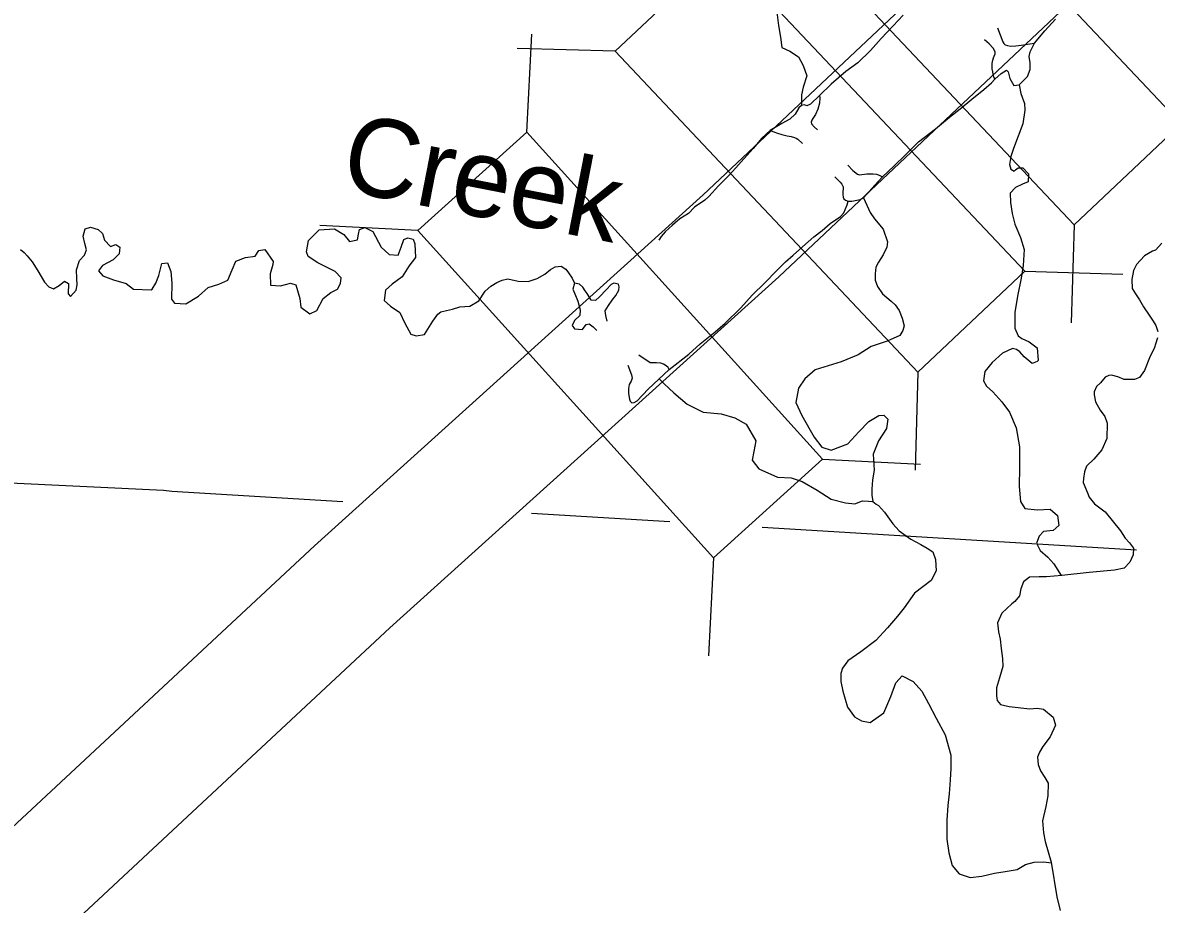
# Model space of a CAD drawing. Extents: x -492261 to -432772, y 1441225 to 1452922.
# Drawn here: x -459293.9 to -459217.6, y 1452255.8 to 1452315.2 of the extents above; entities that cross this region are included whole.
import ezdxf

# ---------------------------------------------------------------- set-up
doc = ezdxf.new("R2010")
doc.units = 0
doc.layers.add('Default', color=7, linetype='Continuous')

msp = doc.modelspace()

# ---------------------------------------------------------------- linework, layer by layer
at = {"layer": 'Default'}
for p, q in [((-459259.942, 1452307.832), (-459259.608, 1452314.423)), ((-459253.993, 1452313.271), (-459260.59, 1452313.464)), ((-459267.287, 1452301.194), (-459273.879, 1452301.528)), ((-459223.1, 1452301.582), (-459223.293, 1452294.985)), ((-459226.413, 1452298.458), (-459219.815, 1452298.265)), ((-459233.615, 1452291.665), (-459233.807, 1452285.068)), ((-459240.031, 1452285.795), (-459233.439, 1452285.461)), ((-459247.376, 1452279.158), (-459247.71, 1452272.566))]:
    msp.add_line(p, q, dxfattribs=at)
for points in [[(-459243.478, 1452323.188), (-459223.1, 1452301.582), (-459215.898, 1452308.375), (-459236.276, 1452329.981)], [(-459226.413, 1452298.458), (-459246.791, 1452320.063), (-459253.993, 1452313.271), (-459233.615, 1452291.665)], [(-459267.287, 1452301.194), (-459247.376, 1452279.158), (-459240.031, 1452285.795), (-459259.942, 1452307.832)]]:
    msp.add_lwpolyline(points, close=True, dxfattribs=at)
for points in [[(-459226.852, 1452323.611), (-459248.072, 1452303.597), (-459274.233, 1452279.959), (-459300.843, 1452255.178), (-459324.123, 1452234.249), (-459334.966, 1452224.74), (-459339.178, 1452220.722), (-459342.089, 1452218.162), (-459344.419, 1452216.641), (-459347.562, 1452215.217), (-459351.068, 1452213.62), (-459355.03, 1452212.272), (-459362.034, 1452210.587), (-459385.935, 1452204.007), (-459423.021, 1452192.768)], [(-459221.706, 1452318.155), (-459242.984, 1452298.086), (-459269.163, 1452274.432), (-459295.78, 1452249.645), (-459319.143, 1452228.64), (-459329.903, 1452219.205), (-459334.111, 1452215.19), (-459337.54, 1452212.176), (-459340.801, 1452210.046), (-459344.461, 1452208.389), (-459348.299, 1452206.64), (-459352.94, 1452205.061), (-459360.161, 1452203.323), (-459383.851, 1452196.802), (-459420.846, 1452185.59)], [(-459249.502, 1452318.521), (-459248.411, 1452317.678), (-459247.93, 1452317.066), (-459247.335, 1452316.421), (-459246.434, 1452316.774), (-459245.69, 1452317.787), (-459244.752, 1452318.154), (-459243.708, 1452317.936), (-459243.173, 1452317.213), (-459243.126, 1452316.087), (-459243.005, 1452315.001), (-459242.868, 1452314.216), (-459242.784, 1452313.53), (-459242.239, 1452313.271), (-459241.652, 1452312.901), (-459241.347, 1452312.321), (-459241.088, 1452311.628), (-459241.339, 1452310.856), (-459241.448, 1452310.339), (-459241.449, 1452309.615)], [(-459234.615, 1452315.702), (-459235.281, 1452314.993), (-459236.079, 1452314.141), (-459236.816, 1452313.317), (-459237.652, 1452312.489), (-459238.471, 1452311.9), (-459239.457, 1452311.055), (-459240.246, 1452310.304), (-459240.84, 1452309.709), (-459241.099, 1452309.588), (-459241.251, 1452309.671), (-459241.449, 1452309.615), (-459241.632, 1452309.459), (-459241.881, 1452309.038), (-459242.233, 1452308.701), (-459242.786, 1452308.409), (-459243.571, 1452307.933), (-459244.118, 1452307.428), (-459244.696, 1452306.733), (-459245.324, 1452306.025), (-459245.881, 1452305.431), (-459246.376, 1452304.89), (-459247.042, 1452304.205), (-459247.682, 1452303.484), (-459247.962, 1452303.237), (-459248.66, 1452302.777), (-459249.071, 1452302.338), (-459249.635, 1452301.983)], [(-459249.037, 1452292.874), (-459248.284, 1452293.573), (-459247.271, 1452294.369), (-459246.602, 1452294.966), (-459245.534, 1452295.989), (-459244.774, 1452296.852), (-459243.924, 1452297.667), (-459243.125, 1452298.494), (-459242.532, 1452299.088), (-459242.021, 1452299.543), (-459241.388, 1452300.101), (-459240.622, 1452300.764), (-459240.06, 1452301.194), (-459239.512, 1452301.662), (-459238.823, 1452302.134), (-459238.597, 1452302.38), (-459238.374, 1452302.924), (-459238.322, 1452303.169), (-459238.065, 1452303.182), (-459237.731, 1452303.233), (-459237.506, 1452303.297), (-459237.28, 1452303.41), (-459236.519, 1452304.261), (-459236.011, 1452304.79), (-459235.222, 1452305.566), (-459234.482, 1452306.278), (-459233.573, 1452307.171), (-459232.425, 1452308.046), (-459231.5, 1452308.838), (-459230.768, 1452309.4), (-459229.988, 1452310.038), (-459229.183, 1452310.689), (-459228.66, 1452311.144), (-459228.43, 1452311.389), (-459228.005, 1452311.766), (-459227.65, 1452312.002), (-459227.546, 1452311.892), (-459227.432, 1452311.445), (-459227.167, 1452310.965), (-459226.794, 1452311.001), (-459226.237, 1452311.57), (-459226.064, 1452312.039), (-459226.053, 1452312.49), (-459226.129, 1452312.926), (-459226.063, 1452313.229), (-459225.757, 1452313.827), (-459225.07, 1452314.638), (-459224.345, 1452315.437)], [(-459228.26, 1452314.857), (-459227.908, 1452313.898), (-459227.841, 1452313.794), (-459227.752, 1452313.703), (-459227.595, 1452313.655), (-459227.388, 1452313.626), (-459227.014, 1452313.642), (-459226.66, 1452313.68), (-459226.363, 1452313.718), (-459226.079, 1452313.762), (-459225.757, 1452313.827)], [(-459228.43, 1452311.389), (-459228.46, 1452311.449), (-459228.498, 1452311.543), (-459228.549, 1452311.733), (-459228.58, 1452311.897), (-459228.606, 1452312.087), (-459228.612, 1452312.454), (-459228.581, 1452312.674), (-459228.53, 1452312.833), (-459228.478, 1452312.953), (-459228.407, 1452313.093), (-459228.41, 1452313.205), (-459228.452, 1452313.329), (-459228.557, 1452313.489), (-459228.812, 1452313.766), (-459229.126, 1452314.049)], [(-459226.794, 1452311.001), (-459226.687, 1452310.418), (-459226.441, 1452309.762), (-459226.427, 1452309.311), (-459226.548, 1452308.38), (-459227.184, 1452306.72), (-459227.355, 1452306.188), (-459227.451, 1452305.646), (-459227.366, 1452305.336), (-459227.125, 1452305.205), (-459227.052, 1452305.283), (-459226.856, 1452305.414), (-459226.544, 1452305.424), (-459226.169, 1452305.009), (-459226.202, 1452304.47), (-459226.572, 1452304.32), (-459227.053, 1452304.093), (-459227.403, 1452303.718), (-459227.384, 1452303.08), (-459227.261, 1452302.357)], [(-459240.246, 1452310.304), (-459240.22, 1452310.128), (-459240.238, 1452309.785), (-459240.347, 1452309.378), (-459240.5, 1452309.017), (-459240.7, 1452308.74), (-459240.767, 1452308.639), (-459240.812, 1452308.504), (-459240.771, 1452308.379), (-459240.599, 1452308.189), (-459240.366, 1452307.989)], [(-459243.571, 1452307.933), (-459243.065, 1452307.748), (-459242.774, 1452307.656), (-459242.422, 1452307.573), (-459242.156, 1452307.526), (-459241.926, 1452307.47), (-459241.813, 1452307.421), (-459241.7, 1452307.345), (-459241.38, 1452307.058)], [(-459238.336, 1452305.61), (-459238.002, 1452305.253), (-459237.677, 1452304.988), (-459237.553, 1452304.961), (-459237.047, 1452305.021), (-459236.637, 1452305.021), (-459236.396, 1452304.985), (-459236.219, 1452304.933), (-459236.053, 1452304.845), (-459236.011, 1452304.79)], [(-459239.204, 1452304.813), (-459238.857, 1452304.454), (-459238.74, 1452304.313), (-459238.655, 1452304.147), (-459238.643, 1452304.004), (-459238.669, 1452303.796), (-459238.669, 1452303.625), (-459238.637, 1452303.452), (-459238.598, 1452303.342), (-459238.496, 1452303.252), (-459238.322, 1452303.169)], [(-459237.28, 1452303.41), (-459236.841, 1452302.419), (-459236.54, 1452301.99), (-459235.944, 1452301.294), (-459235.655, 1452300.439), (-459235.706, 1452300.078), (-459235.952, 1452299.553), (-459236.265, 1452299.075), (-459236.451, 1452298.735), (-459236.499, 1452298.277), (-459236.487, 1452297.857), (-459236.333, 1452297.431), (-459236.009, 1452296.945)], [(-459227.261, 1452302.357), (-459227.098, 1452301.634), (-459226.714, 1452300.721), (-459226.464, 1452299.927), (-459226.53, 1452298.848), (-459226.654, 1452297.992), (-459226.903, 1452296.769), (-459227.095, 1452295.686), (-459227.087, 1452294.634), (-459226.87, 1452294.102), (-459226.628, 1452293.934), (-459226.134, 1452293.711), (-459225.583, 1452293.289), (-459225.519, 1452292.439), (-459225.58, 1452292.375), (-459225.926, 1452292.252), (-459226.464, 1452292.698), (-459226.763, 1452293.04), (-459226.98, 1452293.196), (-459227.256, 1452293.25), (-459227.922, 1452292.941), (-459228.627, 1452292.318), (-459229.121, 1452291.714), (-459229.201, 1452291.073), (-459228.99, 1452290.716), (-459228.565, 1452290.328), (-459227.958, 1452289.67), (-459227.461, 1452288.959), (-459226.991, 1452287.921), (-459226.776, 1452286.638), (-459226.783, 1452285.259), (-459226.805, 1452283.956), (-459226.712, 1452282.944), (-459226.422, 1452282.477), (-459225.595, 1452282.389), (-459224.722, 1452282.442), (-459224.221, 1452282.018), (-459224.137, 1452281.332), (-459224.502, 1452281.008), (-459225.162, 1452280.937), (-459225.452, 1452280.615), (-459225.637, 1452280.146), (-459225.385, 1452279.652), (-459224.871, 1452279.205), (-459224.47, 1452278.753), (-459223.971, 1452277.959)], [(-459289.721, 1452299.549), (-459289.581, 1452299.892), (-459289.695, 1452300.327), (-459289.81, 1452300.812), (-459289.675, 1452301.304), (-459289.316, 1452301.416), (-459288.799, 1452301.269), (-459288.503, 1452300.99), (-459288.365, 1452300.556), (-459287.964, 1452300.117), (-459287.618, 1452300.253), (-459287.35, 1452300.073), (-459287.399, 1452299.621), (-459287.799, 1452299.233), (-459288.512, 1452298.847), (-459288.775, 1452298.488), (-459288.477, 1452298.147), (-459287.769, 1452297.868), (-459286.924, 1452297.631), (-459286.413, 1452297.246), (-459285.236, 1452297.195), (-459285.176, 1452297.259), (-459284.925, 1452297.643), (-459284.717, 1452298.175), (-459284.517, 1452298.971), (-459284.131, 1452299.033), (-459283.913, 1452298.438), (-459283.839, 1452297.664), (-459283.855, 1452296.586), (-459283.672, 1452296.303), (-459282.896, 1452296.265), (-459282.049, 1452296.779), (-459281.405, 1452297.363), (-459280.688, 1452297.598), (-459280.083, 1452297.855), (-459279.78, 1452298.541), (-459279.536, 1452299.137), (-459278.894, 1452299.383), (-459278.234, 1452299.466), (-459277.983, 1452299.849), (-459277.586, 1452299.924), (-459277.023, 1452299.115), (-459277.042, 1452298.914), (-459277.223, 1452298.282), (-459277.199, 1452297.518), (-459276.535, 1452297.476), (-459275.854, 1452297.66), (-459275.5, 1452297.546), (-459275.234, 1452296.614), (-459275.153, 1452296.028), (-459274.552, 1452295.596), (-459274.085, 1452295.823), (-459273.647, 1452296.626), (-459273.147, 1452297.017), (-459272.692, 1452297.257), (-459272.479, 1452297.627), (-459272.453, 1452298.016), (-459272.853, 1452298.43), (-459274.021, 1452299.02), (-459274.659, 1452299.439), (-459274.782, 1452299.773), (-459274.643, 1452300.517), (-459273.928, 1452301.253), (-459272.893, 1452301.31), (-459272.256, 1452300.929), (-459271.879, 1452300.464), (-459271.345, 1452300.568), (-459271.282, 1452300.959), (-459271.205, 1452301.274), (-459270.859, 1452301.41), (-459270.313, 1452301.127), (-459269.743, 1452300.079), (-459269.215, 1452299.582), (-459268.615, 1452299.55), (-459268.406, 1452300.083), (-459268.222, 1452300.59), (-459267.963, 1452300.698), (-459267.598, 1452300.622), (-459267.476, 1452300.312), (-459267.447, 1452299.374), (-459267.891, 1452298.796), (-459268.331, 1452298.081), (-459269.016, 1452297.596), (-459269.453, 1452297.182), (-459269.544, 1452296.477), (-459269.12, 1452296.102), (-459268.482, 1452295.683), (-459268.159, 1452294.954), (-459267.75, 1452294.228), (-459267.396, 1452294.113), (-459266.837, 1452294.206), (-459266.597, 1452294.551), (-459266.277, 1452295.1), (-459265.929, 1452295.574), (-459265.734, 1452295.718), (-459265.362, 1452295.805), (-459264.952, 1452295.905), (-459264.445, 1452296.059), (-459263.773, 1452296.105), (-459263.182, 1452296.455), (-459262.747, 1452297.12)], [(-459249.635, 1452301.983), (-459250.142, 1452301.558), (-459250.639, 1452301.112), (-459250.904, 1452300.803), (-459251.046, 1452300.548)], [(-459294.025, 1452299.932), (-459293.774, 1452299.72), (-459293.571, 1452299.496), (-459293.245, 1452299.088), (-459292.857, 1452298.496), (-459292.413, 1452297.712), (-459292.123, 1452297.415), (-459291.812, 1452297.279), (-459291.432, 1452297.504), (-459291.078, 1452297.791), (-459290.798, 1452297.636), (-459290.814, 1452296.947), (-459290.658, 1452296.751), (-459290.272, 1452297.189), (-459290.208, 1452297.542), (-459290.234, 1452297.967), (-459290.265, 1452298.555), (-459290.059, 1452299.188), (-459289.721, 1452299.549)], [(-459217.184, 1452300.359), (-459217.632, 1452299.883), (-459217.832, 1452299.807), (-459218.355, 1452299.506), (-459218.903, 1452298.904), (-459219.102, 1452298.504), (-459219.225, 1452297.902), (-459219.199, 1452297.301), (-459218.974, 1452296.926), (-459218.699, 1452296.526), (-459218.424, 1452296.05), (-459218.049, 1452295.5), (-459217.774, 1452295.1), (-459217.598, 1452294.8), (-459217.473, 1452294.399)], [(-459217.184, 1452300.359), (-459217.632, 1452299.883), (-459217.832, 1452299.807), (-459218.355, 1452299.506), (-459218.903, 1452298.904), (-459219.102, 1452298.504), (-459219.225, 1452297.902), (-459219.199, 1452297.301), (-459218.974, 1452296.926), (-459218.699, 1452296.526), (-459218.424, 1452296.05), (-459218.049, 1452295.5), (-459217.774, 1452295.1), (-459217.598, 1452294.8), (-459217.473, 1452294.399)], [(-459262.747, 1452297.12), (-459262.373, 1452297.446), (-459261.963, 1452297.7), (-459261.601, 1452297.857), (-459261.233, 1452297.952), (-459260.528, 1452297.799), (-459259.852, 1452297.769), (-459259.246, 1452297.976), (-459258.73, 1452298.255), (-459258.34, 1452298.568), (-459258.046, 1452298.752), (-459257.635, 1452298.803), (-459257.329, 1452298.599), (-459257.134, 1452298.355), (-459256.897, 1452297.986), (-459256.724, 1452297.649)], [(-459254.534, 1452295.094), (-459254.632, 1452295.471), (-459254.68, 1452295.796), (-459254.441, 1452296.141), (-459254.202, 1452296.499), (-459253.95, 1452296.821), (-459253.749, 1452297.19), (-459253.718, 1452297.404), (-459253.773, 1452297.59), (-459254.088, 1452297.656), (-459254.272, 1452297.562), (-459254.612, 1452297.213), (-459255.059, 1452296.736), (-459255.314, 1452296.49), (-459255.602, 1452296.506), (-459255.878, 1452296.949), (-459256.009, 1452297.145), (-459256.166, 1452297.378), (-459256.398, 1452297.597), (-459256.724, 1452297.649), (-459256.837, 1452297.245), (-459256.702, 1452296.936), (-459256.512, 1452296.453), (-459256.344, 1452295.857), (-459256.369, 1452295.468), (-459256.734, 1452295.131), (-459256.886, 1452294.813), (-459256.729, 1452294.58), (-459256.203, 1452294.533), (-459255.938, 1452294.867), (-459255.752, 1452294.911), (-459255.484, 1452294.718), (-459255.227, 1452294.464)], [(-459236.009, 1452296.945), (-459235.419, 1452296.448), (-459235.157, 1452296.205), (-459234.871, 1452295.808), (-459234.68, 1452295.3), (-459234.552, 1452294.778), (-459234.636, 1452294.472), (-459234.831, 1452294.131), (-459235.682, 1452293.754), (-459236.77, 1452293.394), (-459237.627, 1452292.817), (-459238.788, 1452292.355), (-459240.533, 1452291.825), (-459241.239, 1452291.202), (-459241.657, 1452290.587), (-459241.827, 1452289.617), (-459241.437, 1452288.74), (-459240.604, 1452287.275), (-459240.084, 1452286.614), (-459239.453, 1452286.408), (-459238.329, 1452286.844), (-459237.592, 1452287.644), (-459236.926, 1452288.328), (-459236.239, 1452288.75), (-459235.902, 1452288.761), (-459235.644, 1452288.506), (-459235.737, 1452287.876), (-459236.261, 1452287.033), (-459236.62, 1452286.145), (-459236.562, 1452285.069), (-459236.679, 1452284.402), (-459236.722, 1452283.774), (-459236.722, 1452283.373), (-459236.659, 1452282.951)], [(-459217.497, 1452293.973), (-459217.621, 1452293.547), (-459217.696, 1452293.322), (-459218.019, 1452292.62), (-459218.366, 1452291.769), (-459218.69, 1452291.292), (-459219.039, 1452291.167), (-459219.438, 1452291.166), (-459219.737, 1452291.166), (-459220.162, 1452291.34), (-459220.586, 1452291.465), (-459220.76, 1452291.44), (-459221.01, 1452291.314), (-459221.333, 1452290.938), (-459221.582, 1452290.687), (-459221.756, 1452290.337), (-459221.756, 1452290.136), (-459221.655, 1452289.661), (-459221.355, 1452289.11), (-459221.03, 1452288.685), (-459220.88, 1452288.234), (-459220.903, 1452287.183), (-459221.226, 1452286.431), (-459221.773, 1452285.804), (-459222.271, 1452285.328), (-459222.395, 1452284.952), (-459222.47, 1452284.501), (-459222.494, 1452284.226), (-459222.193, 1452283.525), (-459222.093, 1452283.25), (-459221.718, 1452282.799), (-459221.019, 1452282.249), (-459219.969, 1452280.974), (-459219.669, 1452280.473), (-459219.369, 1452280.173), (-459219.094, 1452279.798), (-459219.118, 1452279.347), (-459219.342, 1452278.871), (-459219.74, 1452278.47), (-459220.388, 1452278.319), (-459222.084, 1452278.166), (-459223.93, 1452277.963), (-459224.952, 1452277.887), (-459225.451, 1452277.886), (-459226.1, 1452277.86), (-459226.498, 1452277.534), (-459226.697, 1452277.058), (-459226.771, 1452276.607), (-459227.095, 1452276.206), (-459227.294, 1452276.056), (-459227.966, 1452275.429), (-459228.265, 1452274.777), (-459228.189, 1452274.176), (-459228.088, 1452273.676), (-459228.012, 1452273.05), (-459227.911, 1452272.374), (-459227.91, 1452271.848), (-459228.133, 1452271.071), (-459228.332, 1452270.395), (-459228.331, 1452269.869), (-459228.28, 1452269.544), (-459228.055, 1452269.269), (-459227.482, 1452269.144), (-459226.084, 1452268.996), (-459225.586, 1452269.022)], [(-459217.497, 1452293.973), (-459217.621, 1452293.547), (-459217.696, 1452293.322), (-459218.019, 1452292.62), (-459218.366, 1452291.769), (-459218.69, 1452291.292), (-459219.039, 1452291.167), (-459219.438, 1452291.166), (-459219.737, 1452291.166), (-459220.162, 1452291.34), (-459220.586, 1452291.465), (-459220.76, 1452291.44), (-459221.01, 1452291.314), (-459221.333, 1452290.938), (-459221.582, 1452290.687), (-459221.756, 1452290.337), (-459221.756, 1452290.136), (-459221.655, 1452289.661), (-459221.355, 1452289.11), (-459221.03, 1452288.685), (-459220.88, 1452288.234), (-459220.903, 1452287.183), (-459221.226, 1452286.431), (-459221.773, 1452285.804), (-459222.271, 1452285.328), (-459222.395, 1452284.952), (-459222.47, 1452284.501), (-459222.494, 1452284.226), (-459222.193, 1452283.525), (-459222.093, 1452283.25), (-459221.718, 1452282.799), (-459221.019, 1452282.249), (-459219.969, 1452280.974), (-459219.669, 1452280.473), (-459219.369, 1452280.173), (-459219.094, 1452279.798), (-459219.118, 1452279.347), (-459219.342, 1452278.871), (-459219.74, 1452278.47), (-459220.388, 1452278.319), (-459222.084, 1452278.166), (-459223.93, 1452277.963), (-459224.952, 1452277.887), (-459225.451, 1452277.886), (-459226.1, 1452277.86), (-459226.498, 1452277.534), (-459226.697, 1452277.058), (-459226.771, 1452276.607), (-459227.095, 1452276.206), (-459227.294, 1452276.056), (-459227.966, 1452275.429), (-459228.265, 1452274.777), (-459228.189, 1452274.176), (-459228.088, 1452273.676), (-459228.012, 1452273.05), (-459227.911, 1452272.374), (-459227.91, 1452271.848), (-459228.133, 1452271.071), (-459228.332, 1452270.395), (-459228.331, 1452269.869), (-459228.28, 1452269.544), (-459228.055, 1452269.269), (-459227.482, 1452269.144), (-459226.084, 1452268.996), (-459225.586, 1452269.022)], [(-459252.879, 1452289.59), (-459252.719, 1452289.617), (-459252.505, 1452289.733), (-459251.772, 1452290.525), (-459250.351, 1452291.847), (-459249.037, 1452292.874)], [(-459253.138, 1452292.139), (-459252.897, 1452291.475), (-459252.862, 1452291.252), (-459252.915, 1452291.064), (-459253.049, 1452290.823), (-459253.094, 1452290.555), (-459253.094, 1452290.224), (-459253.031, 1452289.84), (-459252.978, 1452289.697), (-459252.879, 1452289.59)], [(-459250.351, 1452291.847), (-459250.425, 1452291.975), (-459250.568, 1452292.091), (-459250.746, 1452292.207), (-459250.916, 1452292.261), (-459251.22, 1452292.295), (-459251.645, 1452292.281), (-459252.407, 1452292.804)], [(-459251.026, 1452291.219), (-459250.688, 1452290.884), (-459250.044, 1452290.265), (-459249.146, 1452289.516), (-459248.08, 1452288.973), (-459246.852, 1452288.86), (-459245.943, 1452288.575), (-459245.168, 1452288.161), (-459244.533, 1452287.04), (-459244.661, 1452286.31), (-459244.78, 1452285.73), (-459244.325, 1452285.155), (-459243.07, 1452284.593), (-459242.144, 1452284.533), (-459241.399, 1452284.293), (-459240.406, 1452283.71), (-459239.463, 1452283.113), (-459238.493, 1452282.867), (-459237.866, 1452282.799), (-459237.335, 1452283.003), (-459236.947, 1452282.978), (-459236.646, 1452282.95), (-459236.429, 1452282.781), (-459236.275, 1452282.673)], [(-459415.906, 1452290.337), (-459350.08, 1452286.899), (-459349.654, 1452286.834), (-459284.411, 1452283.707), (-459283.835, 1452283.646), (-459272.338, 1452282.945)], [(-459259.628, 1452282.169), (-459250.323, 1452281.602)], [(-459236.275, 1452282.673), (-459235.861, 1452282.222), (-459235.312, 1452281.437), (-459234.873, 1452280.975), (-459234.093, 1452280.41), (-459233.419, 1452280.043), (-459232.988, 1452279.818), (-459232.604, 1452279.554), (-459232.426, 1452279.034), (-459232.39, 1452278.283), (-459232.719, 1452277.621), (-459233.843, 1452276.772), (-459234.549, 1452275.786), (-459234.982, 1452275.221), (-459235.657, 1452274.436), (-459236.443, 1452273.597), (-459237.457, 1452272.827), (-459238.325, 1452272.224), (-459238.697, 1452271.736), (-459238.811, 1452271.369), (-459238.807, 1452270.831), (-459238.662, 1452270.184), (-459238.353, 1452269.091), (-459237.883, 1452268.454), (-459237.412, 1452268.18), (-459236.834, 1452268.06), (-459235.917, 1452268.727), (-459235.438, 1452269.807), (-459235.092, 1452270.732), (-459234.67, 1452271.209), (-459233.945, 1452270.818), (-459233.351, 1452270.185), (-459232.9, 1452269.347), (-459232.382, 1452268.348), (-459231.784, 1452267.227), (-459231.405, 1452265.873), (-459231.402, 1452264.971), (-459231.441, 1452264.205), (-459231.511, 1452263.251), (-459231.6, 1452262.484), (-459231.669, 1452261.492), (-459231.666, 1452260.202), (-459231.538, 1452259.291), (-459231.299, 1452258.434), (-459230.832, 1452257.872), (-459230.087, 1452257.632), (-459229.315, 1452257.706), (-459228.459, 1452257.921), (-459227.75, 1452258.03), (-459226.93, 1452258.168), (-459226.378, 1452258.499), (-459225.783, 1452258.667), (-459225.146, 1452258.675), (-459224.637, 1452258.609)], [(-459244.109, 1452281.223), (-459218.894, 1452279.684)], [(-459225.586, 1452269.022), (-459225.161, 1452268.972), (-459224.512, 1452268.422), (-459224.361, 1452267.896), (-459224.709, 1452267.095), (-459225.207, 1452266.443), (-459225.431, 1452266.067), (-459225.555, 1452265.741), (-459225.529, 1452265.24), (-459225.354, 1452264.815), (-459225.078, 1452264.365), (-459224.853, 1452263.989), (-459224.877, 1452263.138), (-459225, 1452262.412), (-459225.223, 1452261.435), (-459225.172, 1452260.633), (-459225.046, 1452260.058), (-459224.644, 1452258.656), (-459224.266, 1452256.328), (-459224.04, 1452255.401)], [(-459225.586, 1452269.022), (-459225.161, 1452268.972), (-459224.512, 1452268.422), (-459224.361, 1452267.896), (-459224.709, 1452267.095), (-459225.207, 1452266.443), (-459225.431, 1452266.067), (-459225.555, 1452265.741), (-459225.529, 1452265.24), (-459225.354, 1452264.815), (-459225.078, 1452264.365), (-459224.853, 1452263.989), (-459224.877, 1452263.138), (-459225, 1452262.412), (-459225.223, 1452261.435), (-459225.172, 1452260.633), (-459225.046, 1452260.058), (-459224.644, 1452258.656), (-459224.266, 1452256.328), (-459224.04, 1452255.401)]]:
    msp.add_lwpolyline(points, dxfattribs=at)

# ---------------------------------------------------------------- texts
msp.add_text('Creek', height=5.28, rotation=348.97138, dxfattribs=at).set_placement((-459272.629, 1452303.97))

doc.saveas('drawing.dxf')
